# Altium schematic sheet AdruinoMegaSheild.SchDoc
size A4; Date: 09 July 2012; Author: Simon Markham; DrawnBy: Simon Markham; Engineer: Simon Markham; Organization: Markham Designs
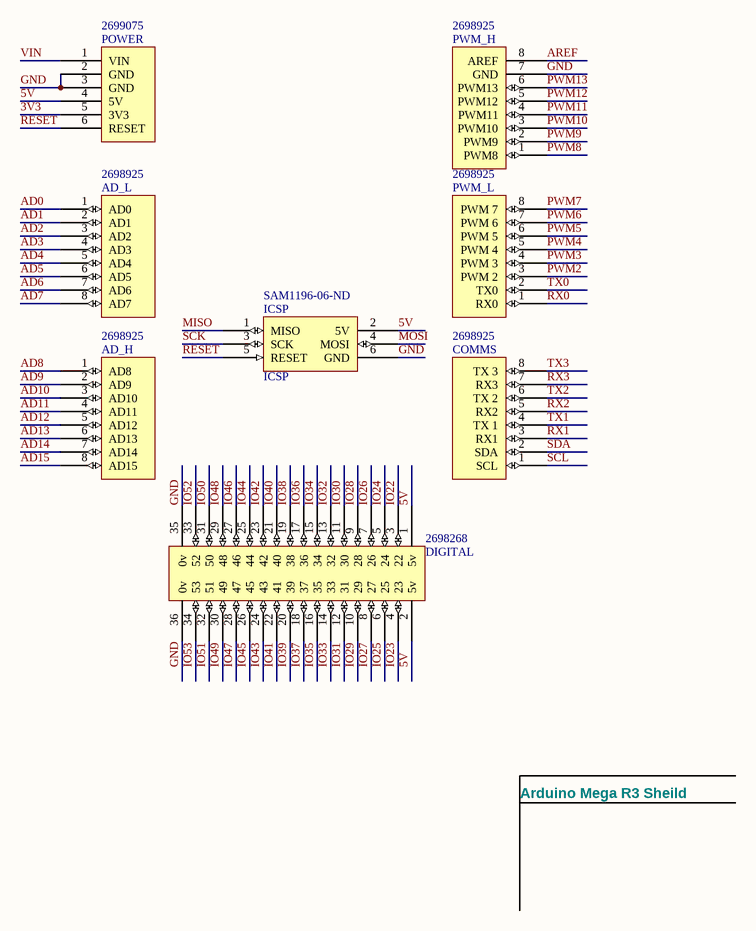
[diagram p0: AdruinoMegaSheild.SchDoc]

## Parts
AD_H  Supplier Part Number 4: 2698925  [Header 8x1 8.5mm]  (hidden comment: AD_H)
AD_L  Supplier Part Number 5: 2698925  [Header 8x1 8.5mm]  (hidden comment: AD_L)
COMMS  Supplier Part Number 4: 2698925  [Header 8x1 8.5mm]  (hidden comment: Communication)
DIGITAL  Supplier Part Number 5: 2698268  [HEADER 36X 8MM]  (hidden comment: IO_36)
ICSP  ICSP  Supplier Part Number 5: SAM1196-06-ND  [ICSP]
POWER  Supplier Part Number 2: 2699075  [Header 6x1 8.5mm]  (hidden comment: POWER)
PWM_H  Supplier Part Number 4: 2698925  [Header 8x1 8.5mm]  (hidden comment: PWM_H)
PWM_L  Supplier Part Number 4: 2698925  [Header 8x1 8.5mm]  (hidden comment: PWM_L)

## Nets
3V3: POWER.5(3V3)
5V: DIGITAL.1(5v) DIGITAL.2(5v) ICSP.2(5V) POWER.4(5V)
AD0: AD_L.1(AD0)
AD1: AD_L.2(AD1)
AD2: AD_L.3(AD2)
AD3: AD_L.4(AD3)
AD4: AD_L.5(AD4)
AD5: AD_L.6(AD5)
AD6: AD_L.7(AD6)
AD7: AD_L.8(AD7)
AD8: AD_H.1(AD8)
AD9: AD_H.2(AD9)
AD10: AD_H.3(AD10)
AD11: AD_H.4(AD11)
AD12: AD_H.5(AD12)
AD13: AD_H.6(AD13)
AD14: AD_H.7(AD14)
AD15: AD_H.8(AD15)
AREF: PWM_H.8(AREF)
GND: DIGITAL.35(0v) DIGITAL.36(0v) ICSP.6(GND) POWER.2(GND) POWER.3(GND) PWM_H.7(GND)
IO22: DIGITAL.3(22)
IO23: DIGITAL.4(23)
IO24: DIGITAL.5(24)
IO25: DIGITAL.6(25)
IO26: DIGITAL.7(26)
IO27: DIGITAL.8(27)
IO28: DIGITAL.9(28)
IO29: DIGITAL.10(29)
IO30: DIGITAL.11(30)
IO31: DIGITAL.12(31)
IO32: DIGITAL.13(32)
IO33: DIGITAL.14(33)
IO34: DIGITAL.15(34)
IO35: DIGITAL.16(35)
IO36: DIGITAL.17(36)
IO37: DIGITAL.18(37)
IO38: DIGITAL.19(38)
IO39: DIGITAL.20(39)
IO40: DIGITAL.21(40)
IO41: DIGITAL.22(41)
IO42: DIGITAL.23(42)
IO43: DIGITAL.24(43)
IO44: DIGITAL.25(44)
IO45: DIGITAL.26(45)
IO46: DIGITAL.27(46)
IO47: DIGITAL.28(47)
IO48: DIGITAL.29(48)
IO49: DIGITAL.30(49)
IO50: DIGITAL.31(50)
IO51: DIGITAL.32(51)
IO52: DIGITAL.33(52)
IO53: DIGITAL.34(53)
MISO: ICSP.1(MISO)
MOSI: ICSP.4(MOSI)
PWM2: PWM_L.3(PWM_2)
PWM3: PWM_L.4(PWM_3)
PWM4: PWM_L.5(PWM_4)
PWM5: PWM_L.6(PWM_5)
PWM6: PWM_L.7(PWM_6)
PWM7: PWM_L.8(PWM_7)
PWM8: PWM_H.1(PWM8)
PWM9: PWM_H.2(PWM9)
PWM10: PWM_H.3(PWM10)
PWM11: PWM_H.4(PWM11)
PWM12: PWM_H.5(PWM12)
PWM13: PWM_H.6(PWM13)
RESET: ICSP.5(RESET) POWER.6(RESET)
RX0: PWM_L.1(RX0)
RX1: COMMS.3(RX1)
RX2: COMMS.5(RX2)
RX3: COMMS.7(RX3)
SCK: ICSP.3(SCK)
SCL: COMMS.1(SCL)
SDA: COMMS.2(SDA)
TX0: PWM_L.2(TX0)
TX1: COMMS.4(TX_1)
TX2: COMMS.6(TX_2)
TX3: COMMS.8(TX_3)
VIN: POWER.1(VIN)

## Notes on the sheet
- Arduino Mega R3 Sheild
